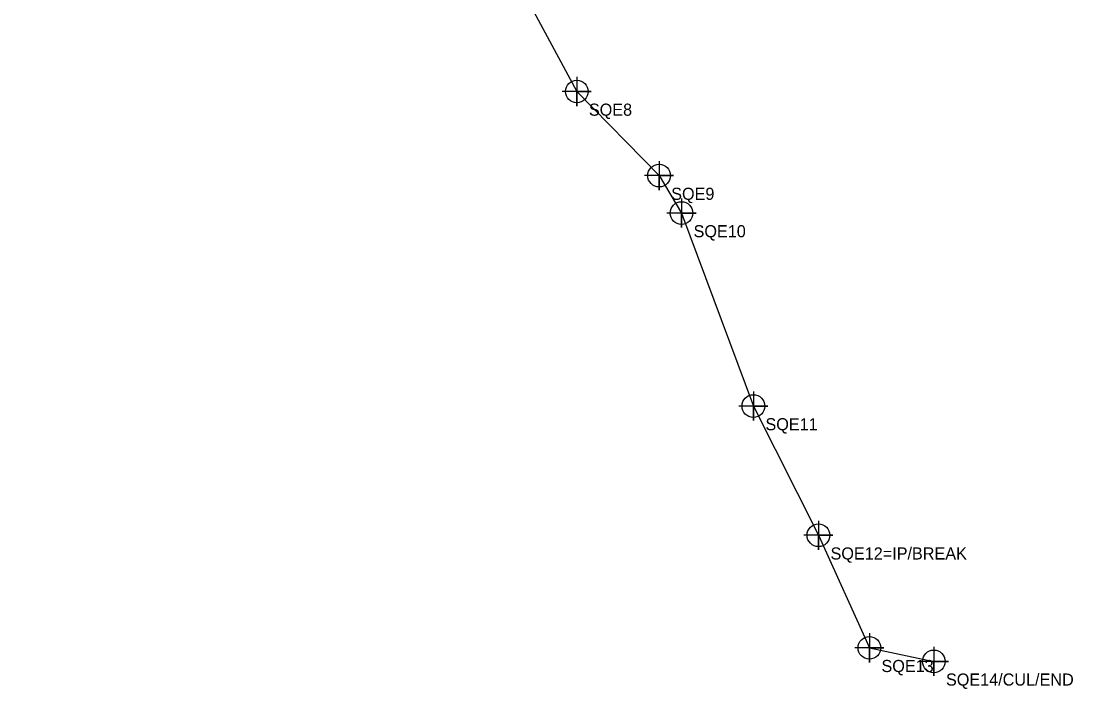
# Model space of a CAD drawing. Extents: x 1705487 to 1707934, y 819100 to 822252.
# Drawn here: x 1705582.6 to 1705799.8, y 821338.6 to 821476.4 of the extents above; entities that cross this region are included whole.
import ezdxf

# ---------------------------------------------------------------- set-up
doc = ezdxf.new("R2010")
doc.units = 0
for name, color, linetype in [('Exist Hydro Jurisdictional Stream or Body of Water Mitigable', 7, 'Continuous'), ('Exist Hydro Jurisdictional Stream or Body of Water NEU Mitigable', 7, 'Continuous'), ('Exist Hydro Jurisdictional Stream or Body of Water NEU Mitigable Cogo Comment', 7, 'Continuous'), ('Exist Hydro Jurisdictional Stream or Body of Water NEU Mitigable Cogo Point CELL', 7, 'Continuous')]:
    doc.layers.add(name, color=color, linetype=linetype)

msp = doc.modelspace()

# ---------------------------------------------------------------- linework, layer by layer
at = {"layer": 'Exist Hydro Jurisdictional Stream or Body of Water Mitigable'}
msp.add_lwpolyline([(1705582.59, 821569.54), (1705590.99, 821564.14), (1705607.1, 821540.73), (1705622.29, 821513.34), (1705633.99, 821504.08), (1705648.75, 821501.86), (1705684.69, 821485.45), (1705697.35, 821461.9), (1705714.35, 821444.54), (1705718.97, 821436.82), (1705733.81, 821397), (1705747.25, 821370.34), (1705757.77, 821347.12), (1705771.09, 821344.32)], dxfattribs=at)
at = {"layer": 'Exist Hydro Jurisdictional Stream or Body of Water NEU Mitigable'}
msp.add_lwpolyline([(1705747.25, 821370.34), (1705757.77, 821347.12), (1705771.09, 821344.32)], dxfattribs=at)
at = {"layer": 'Exist Hydro Jurisdictional Stream or Body of Water NEU Mitigable Cogo Point CELL'}
for points in [[(1705697.35, 821464.9), (1705697.35, 821458.9), (1705697.35, 821461.9), (1705700.35, 821461.9), (1705694.35, 821461.9)], [(1705714.35, 821447.54), (1705714.35, 821441.54), (1705714.35, 821444.54), (1705717.35, 821444.54), (1705711.35, 821444.54)], [(1705718.97, 821439.82), (1705718.97, 821433.82), (1705718.97, 821436.82), (1705721.97, 821436.82), (1705715.97, 821436.82)], [(1705733.81, 821400), (1705733.81, 821394), (1705733.81, 821397), (1705736.81, 821397), (1705730.81, 821397)], [(1705747.25, 821373.34), (1705747.25, 821367.34), (1705747.25, 821370.34), (1705750.25, 821370.34), (1705744.25, 821370.34)], [(1705757.77, 821350.12), (1705757.77, 821344.12), (1705757.77, 821347.12), (1705760.77, 821347.12), (1705754.77, 821347.12)], [(1705771.09, 821347.32), (1705771.09, 821341.32), (1705771.09, 821344.32), (1705774.09, 821344.32), (1705768.09, 821344.32)]]:
    msp.add_lwpolyline(points, dxfattribs=at)
for centre in [(1705697.35, 821461.9), (1705714.35, 821444.54), (1705718.97, 821436.82), (1705733.81, 821397), (1705747.25, 821370.34), (1705757.77, 821347.12), (1705771.09, 821344.32)]:
    msp.add_circle(centre, 2.34, dxfattribs=at)

# ---------------------------------------------------------------- texts
at = {"layer": 'Exist Hydro Jurisdictional Stream or Body of Water NEU Mitigable Cogo Comment'}
for s, p in [('SQE8', (1705699.85, 821456.9)), ('SQE9', (1705716.85, 821439.54)), ('SQE10', (1705721.47, 821431.82)), ('SQE11', (1705736.31, 821392)), ('SQE12=IP/BREAK', (1705749.75, 821365.34)), ('SQE13', (1705760.27, 821342.12)), ('SQE14/CUL/END', (1705773.59, 821339.32))]:
    msp.add_text(s, height=2.5, dxfattribs=at).set_placement(p)

doc.saveas('drawing.dxf')
